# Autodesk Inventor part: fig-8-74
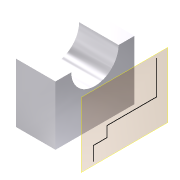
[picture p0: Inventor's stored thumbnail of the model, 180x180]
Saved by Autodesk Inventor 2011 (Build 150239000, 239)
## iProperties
Shininess: 77.0
Length Units: 11269
Angle Units: 11279
Time Units: 11290
Mass Units: 11283
Length Display Precision: 3
Angle Display Precision: 2
Created: 2002-01
Part Number: fig-8-74
Document SubType Name: Modeling
Designer: ***
Density: 1 g/cm^3
Density: 0.0
Volumn: 0.0
Area: 0.0
PropertySet Name: Model Information
Control State: 0
Master: False
Checked Out: False
Author: ***
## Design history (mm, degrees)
sketch "Sketch5"
  geometry: L1 (-22.226, 10.275)-(-14.226, 10.275); L2 (9.774, 10.275)-(17.774, 10.275); L3 (17.774, 10.275)-(17.774, -19.725); L4 (17.774, -19.725)-(-22.226, -19.725); L5 (-22.226, -19.725)-(-22.226, 10.275); A1 r 12 centre (-2.226, 10.275) between (-14.226, 10.275) and (9.774, 10.275)
  constraints: 10 end point, 2 equal length, 2 parallel, 2 point on circle, 1 centre point, 1 collinear, 1 horizontal, 1 perpendicular, 1 point on line
  dimensions: "d7" = 40 distance of L3.end L4.end; "d8" = 30 distance of L2.end L3.end; "d9" = 12 radius of A1
extrude "Extrusion2" new body sketch "Sketch5" distance "d10" = 20; taper "d11" = 0 deg
workplane "Work Plane3"
sketch "Sketch6"
  geometry: L1 (19.321, -18.091)-(12.314, -18.091); L2 (12.314, -18.091)-(12.314, -11.217); L3 (12.314, -11.217)-(7.026, -11.217); L4 (7.026, -11.217)-(7.026, 7.425); L5 (7.026, 7.425)-(7.026, 14.035); L6 (7.026, 14.035)-(-10.029, 14.035)
  constraints: 12 end point, 4 parallel, 1 horizontal, 1 perpendicular
body "Solid1"
other parameters: "d12" = 15
